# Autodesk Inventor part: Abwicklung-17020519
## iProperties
Shininess: 25.0
Length Units: 11269
Angle Units: 11279
Time Units: 11290
Mass Units: 11283
Length Display Precision: 3
Angle Display Precision: 2
Created: 2005-02
Part Number: Abwicklung-17020519
Material: S355NC
Document SubType Name: Blech
Designer: mczerniecki
Density: 0.0
Volumn: 0.0
Area: 0.0
PropertySet Name: Model Information
Control State: 0
Master: False
Checked Out: False
Author: mczerniecki
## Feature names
1. Extrusion1
2. Extrusion2
3. Eckenrundung1
4. Eckenfase1
5. Extrusion3
6. Extrusion4
7. Rechteckige Anordnung1 [Rectangular Pattern]
8. Extrusion7
9. Extrusion8
10. Rundung1 [Fillet]
11. Biegung24
12. Biegung25
13. Biegung26
14. Biegung27
15. Biegung28
16. Biegung29
17. Biegung30
18. Biegung31
19. Biegung32
20. Biegung33
21. Biegung34
22. Biegung35
23. Biegung36
24. Biegung37
25. Biegung38
26. Biegung39
27. Extrusion9
28. Extrusion10
